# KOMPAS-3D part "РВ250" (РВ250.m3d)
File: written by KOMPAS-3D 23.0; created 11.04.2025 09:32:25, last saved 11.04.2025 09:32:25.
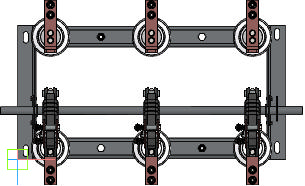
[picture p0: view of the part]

Document properties: Автор: pc; Полное имя файла: C:\Users\pc\Desktop\работа\РВЗ\3D макеты\РВ250.m3d

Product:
- Body: Тело 1
    Масса: 0.01131
- Body: Тело 2
    Масса: 0.01131
- Body: Тело 3
    Масса: 0.052628
- Body: Тело 4
    Масса: 0.052628
- Body: Тело 5
    Масса: 1.849184
- Part/product: РВ250
    Масса: 1.977059

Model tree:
1. Операция без истории:1
2. Операция без истории:2
3. Операция без истории:3
4. Операция без истории:4
5. Операция без истории:5
6. Поверхность без истории:1
7. Поверхность без истории:2
8. Поверхность без истории:3
9. Поверхность без истории:4
10. Поверхность без истории:5
11. Поверхность без истории:6
12. Поверхность без истории:7
13. Поверхность без истории:8
14. Поверхность без истории:9
15. Поверхность без истории:10
16. Поверхность без истории:11
17. Поверхность без истории:12
18. Поверхность без истории:13
19. Поверхность без истории:14
20. Поверхность без истории:15
21. Поверхность без истории:16
22. Поверхность без истории:17
23. Поверхность без истории:18
24. Поверхность без истории:19
25. Поверхность без истории:20
26. Поверхность без истории:21
27. Поверхность без истории:22
28. Поверхность без истории:23
29. Поверхность без истории:24
30. Поверхность без истории:25
31. Поверхность без истории:26
32. Поверхность без истории:27
33. Поверхность без истории:28
34. Поверхность без истории:29
35. Поверхность без истории:30
36. Поверхность без истории:31
37. Поверхность без истории:32
38. Поверхность без истории:33
39. Поверхность без истории:34
40. Поверхность без истории:35
41. Поверхность без истории:36
42. Поверхность без истории:37
43. Поверхность без истории:38
44. Поверхность без истории:39
45. Поверхность без истории:40
46. Поверхность без истории:41
47. Поверхность без истории:42
48. Поверхность без истории:43
49. Поверхность без истории:44
50. Поверхность без истории:45
51. Поверхность без истории:46
52. Поверхность без истории:47
53. Поверхность без истории:48
54. Поверхность без истории:49
55. Поверхность без истории:50
56. Поверхность без истории:51
57. Поверхность без истории:52
58. Поверхность без истории:53
59. Поверхность без истории:54
60. Поверхность без истории:55
61. Поверхность без истории:56
62. Поверхность без истории:57
63. Поверхность без истории:58
64. Поверхность без истории:59
65. Поверхность без истории:60
66. Поверхность без истории:61
67. Поверхность без истории:62
68. Поверхность без истории:63
69. Поверхность без истории:64
70. Поверхность без истории:65
71. Поверхность без истории:66
72. Поверхность без истории:67
73. Поверхность без истории:68
74. Поверхность без истории:69
75. Поверхность без истории:70
76. Поверхность без истории:71
77. Поверхность без истории:72
78. Поверхность без истории:73
79. Поверхность без истории:74
80. Поверхность без истории:75
81. Поверхность без истории:76
82. Поверхность без истории:77
83. Поверхность без истории:78
84. Поверхность без истории:79
85. Поверхность без истории:80
86. Поверхность без истории:81
87. Поверхность без истории:82
88. Поверхность без истории:83
89. Поверхность без истории:84
90. Поверхность без истории:85
91. Поверхность без истории:86
92. Поверхность без истории:87
93. Поверхность без истории:88
94. Поверхность без истории:89
95. Поверхность без истории:90
96. Поверхность без истории:91
97. Поверхность без истории:92
98. Поверхность без истории:93
99. Поверхность без истории:94
100. Поверхность без истории:95
101. Поверхность без истории:96
102. Поверхность без истории:97
103. Поверхность без истории:98
104. Поверхность без истории:99
105. Поверхность без истории:100
106. Поверхность без истории:101
107. Поверхность без истории:102
108. Поверхность без истории:103
109. Поверхность без истории:104
110. Поверхность без истории:105
111. Поверхность без истории:106
112. Поверхность без истории:107
113. Поверхность без истории:108
114. Поверхность без истории:109
115. Поверхность без истории:110
116. Поверхность без истории:111
117. Поверхность без истории:112
118. Поверхность без истории:113
119. Поверхность без истории:114
120. Поверхность без истории:115
121. Поверхность без истории:116
122. Поверхность без истории:117
123. Поверхность без истории:118
124. Поверхность без истории:119
125. Поверхность без истории:120
126. Поверхность без истории:121
127. Поверхность без истории:122
128. Поверхность без истории:123
129. Поверхность без истории:124
130. Поверхность без истории:125
131. Поверхность без истории:126
132. Поверхность без истории:127
133. Поверхность без истории:128
134. Поверхность без истории:129
135. Поверхность без истории:130
136. Поверхность без истории:131
137. Поверхность без истории:132
138. Поверхность без истории:133
139. Поверхность без истории:134
140. Поверхность без истории:135
141. Поверхность без истории:136
142. Поверхность без истории:137
143. Поверхность без истории:138
144. Поверхность без истории:139
145. Поверхность без истории:140
146. Поверхность без истории:141
147. Поверхность без истории:142
148. Поверхность без истории:143
149. Поверхность без истории:144
150. Поверхность без истории:145
151. Поверхность без истории:146
152. Поверхность без истории:147
153. Поверхность без истории:148
154. Поверхность без истории:149
155. Поверхность без истории:150
156. Поверхность без истории:151
157. Поверхность без истории:152
158. Поверхность без истории:153
159. Поверхность без истории:154
160. Поверхность без истории:155
161. Поверхность без истории:156
162. Поверхность без истории:157
163. Поверхность без истории:158
164. Поверхность без истории:159
165. Поверхность без истории:160
166. Поверхность без истории:161
167. Поверхность без истории:162
168. Поверхность без истории:163
169. Поверхность без истории:164
170. Поверхность без истории:165
171. Поверхность без истории:166
172. Поверхность без истории:167
173. Поверхность без истории:168
174. Поверхность без истории:169
175. Поверхность без истории:170
176. Поверхность без истории:171
177. Поверхность без истории:172
178. Поверхность без истории:173
179. Поверхность без истории:174
180. Поверхность без истории:175
181. Поверхность без истории:176
182. Поверхность без истории:177
183. Поверхность без истории:178
184. Поверхность без истории:179
185. Поверхность без истории:180
186. Поверхность без истории:181
187. Поверхность без истории:182
188. Поверхность без истории:183
189. Поверхность без истории:184
190. Поверхность без истории:185
191. Поверхность без истории:186
192. Поверхность без истории:187
193. Поверхность без истории:188
194. Поверхность без истории:189
195. Поверхность без истории:190
196. Поверхность без истории:191
197. Поверхность без истории:192
198. Поверхность без истории:193
199. Поверхность без истории:194
200. Поверхность без истории:195
201. Поверхность без истории:196
202. Поверхность без истории:197
203. Поверхность без истории:198
204. Поверхность без истории:199
205. Поверхность без истории:200
206. Поверхность без истории:201
207. Поверхность без истории:202
208. Поверхность без истории:203
209. Поверхность без истории:204
210. Поверхность без истории:205
211. Поверхность без истории:206
212. Поверхность без истории:207
213. Поверхность без истории:208
214. Поверхность без истории:209
215. Поверхность без истории:210
216. Поверхность без истории:211
217. Поверхность без истории:212
218. Поверхность без истории:213
219. Поверхность без истории:214
220. Поверхность без истории:215
221. Поверхность без истории:216
222. Поверхность без истории:217
223. Поверхность без истории:218
224. Поверхность без истории:219
225. Поверхность без истории:220
226. Поверхность без истории:221
227. Поверхность без истории:222
228. Поверхность без истории:223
